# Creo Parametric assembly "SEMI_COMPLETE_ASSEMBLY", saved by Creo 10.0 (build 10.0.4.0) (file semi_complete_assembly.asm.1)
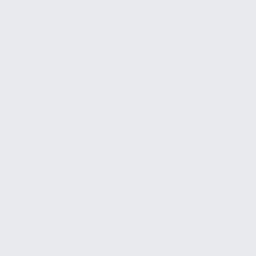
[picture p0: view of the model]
Units: millimeter Kilogram Sec (mmKs); MM, KILOGRAM, SECS

Created from: XX_MMKS_ASM_DESIGN_ABS.ASM

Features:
  1. datum plane "ASM_RIGHT"
  2. datum plane "ASM_TOP"
  3. datum plane "ASM_FRONT"
  4. coordinate system
  5. component "TOP_ASSEMBLY"
  6. component "MECHANISM_ASSEMBLY"
  7. component "BOTTOM_FRAME.PRT"
  8. component "M3_SCREW.PRT"
  9. component "PRT0002.PRT"
  10. component "M3_SCREW.PRT"
  11. component "PRT0003.PRT"

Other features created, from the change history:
  component "PRT0001.PRT"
